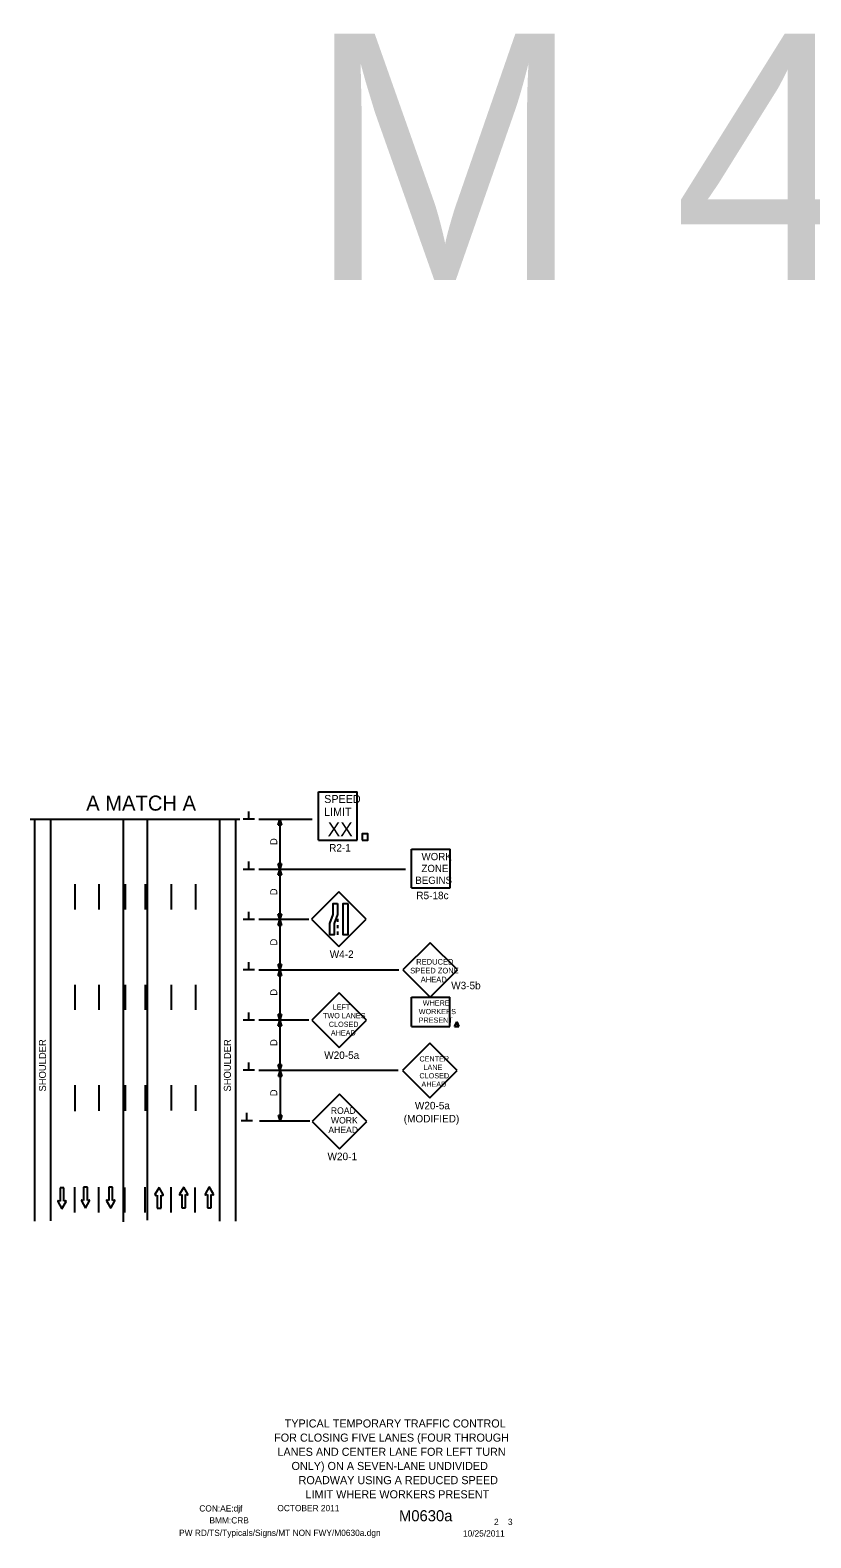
# Model space of a CAD drawing. Extents: x 20837 to 23689, y 414 to 2167.
# Drawn here: x 22136 to 22912, y 667 to 2167 of the extents above; entities that cross this region are included whole.
import ezdxf

# ---------------------------------------------------------------- set-up
doc = ezdxf.new("R2010")
doc.units = 0
for name, color, linetype in [('ALI_LEGAL_EX', 7, 'Continuous'), ('BORDER', 7, 'Continuous'), ('BORDER_SIGNAL_WO', 7, 'Continuous'), ('MT_SCRATCH_LEVEL_E', 7, 'Continuous'), ('PAVT_EDGE_EX', 7, 'Continuous'), ('TRAFFIC_SIGNS_PR', 7, 'Continuous'), ('TYPICAL_TEXT_DIMEN_PR', 7, 'Continuous')]:
    doc.layers.add(name, color=color, linetype=linetype)

msp = doc.modelspace()

# ---------------------------------------------------------------- linework, layer by layer
at = {"layer": 'ALI_LEGAL_EX'}
for points in [[(22180.1, 1317.4), (22180.1, 1292.4)], [(22204.1, 1317.4), (22204.1, 1292.4)], [(22230.1, 1317.4), (22230.1, 1292.4)], [(22250.1, 1317.4), (22250.1, 1292.4)], [(22276.1, 1317.4), (22276.1, 1292.4)], [(22300.1, 1317.4), (22300.1, 1292.4)], [(22180.1, 1217.4), (22180.1, 1192.4)], [(22204.1, 1217.4), (22204.1, 1192.4)], [(22230.1, 1217.4), (22230.1, 1192.4)], [(22250.1, 1217.4), (22250.1, 1192.4)], [(22276.1, 1217.4), (22276.1, 1192.4)], [(22300.1, 1217.4), (22300.1, 1192.4)], [(22180.1, 1117.4), (22180.1, 1091.6)], [(22204.1, 1117.4), (22204.1, 1091.9)], [(22230.1, 1117.4), (22230.1, 1091.9)], [(22250.1, 1117.4), (22250.1, 1091.9)], [(22276.1, 1117.4), (22276.1, 1092.2)], [(22300.1, 1117.4), (22300.1, 1091.9)], [(22180.1, 990.9), (22180.1, 1016)], [(22204, 990.9), (22204, 1016)], [(22229.9, 990.7), (22229.9, 1015.8)], [(22250.2, 990.9), (22250.2, 1016)], [(22276, 990.9), (22276, 1016)], [(22300, 990.7), (22300, 1015.8)]]:
    msp.add_lwpolyline(points, dxfattribs=at)
at = {"layer": 'BORDER'}
msp.add_line((22502.6, 746.5), (22502.6, 746.5), dxfattribs=at)
at = {"layer": 'BORDER_SIGNAL_WO'}
msp.add_line((22502.6, 740.2), (22502.6, 740.2), dxfattribs=at)
at = {"layer": 'MT_SCRATCH_LEVEL_E'}
for p, q in [((22169.2, 1015.4), (22165.5, 1015.4)), ((22165.5, 1015.4), (22165.5, 1002.2)), ((22169.2, 1015.4), (22165.5, 1015.4)), ((22165.5, 1015.4), (22165.5, 1002.2)), ((22169.2, 1002.2), (22169.2, 1015.4)), ((22169.2, 1002.2), (22169.2, 1015.4)), ((22192.7, 1016), (22188.9, 1016)), ((22188.9, 1016), (22188.9, 1002.7)), ((22192.7, 1016), (22188.9, 1016)), ((22188.9, 1016), (22188.9, 1002.7)), ((22192.7, 1002.7), (22192.7, 1016)), ((22192.7, 1002.7), (22192.7, 1016)), ((22217.8, 1016.1), (22214, 1016.1)), ((22214, 1016.1), (22214, 1002.8)), ((22217.8, 1016.1), (22214, 1016.1)), ((22214, 1016.1), (22214, 1002.8)), ((22217.8, 1002.8), (22217.8, 1016.1)), ((22217.8, 1002.8), (22217.8, 1016.1)), ((22264, 1015.8), (22259.9, 1008.6)), ((22264, 1015.8), (22259.9, 1008.6)), ((22260.4, 1007.9), (22262.1, 1008.2)), ((22260.4, 1007.9), (22262.1, 1008.2)), ((22262.1, 1008.2), (22262.1, 995)), ((22262.1, 1008.2), (22262.1, 995)), ((22268.1, 1008.6), (22264, 1015.8)), ((22268.1, 1008.6), (22264, 1015.8)), ((22265.9, 995), (22265.9, 1008.2)), ((22265.9, 1008.2), (22267.6, 1007.9)), ((22265.9, 995), (22265.9, 1008.2)), ((22265.9, 1008.2), (22267.6, 1007.9)), ((22288.5, 1016.2), (22284.4, 1009)), ((22288.5, 1016.2), (22284.4, 1009)), ((22284.9, 1008.3), (22286.7, 1008.6)), ((22284.9, 1008.3), (22286.7, 1008.6)), ((22286.7, 1008.6), (22286.7, 995.4)), ((22286.7, 1008.6), (22286.7, 995.4)), ((22292.7, 1009), (22288.5, 1016.2)), ((22292.7, 1009), (22288.5, 1016.2)), ((22290.4, 995.4), (22290.4, 1008.6)), ((22290.4, 1008.6), (22292.2, 1008.3)), ((22290.4, 995.4), (22290.4, 1008.6)), ((22290.4, 1008.6), (22292.2, 1008.3)), ((22313.8, 1016.3), (22309.7, 1009.1)), ((22313.8, 1016.3), (22309.7, 1009.1)), ((22310.2, 1008.4), (22312, 1008.7)), ((22310.2, 1008.4), (22312, 1008.7)), ((22312, 1008.7), (22312, 995.4)), ((22312, 1008.7), (22312, 995.4)), ((22318, 1009.1), (22313.8, 1016.3)), ((22318, 1009.1), (22313.8, 1016.3)), ((22315.7, 995.4), (22315.7, 1008.7)), ((22315.7, 1008.7), (22317.5, 1008.4)), ((22315.7, 995.4), (22315.7, 1008.7)), ((22315.7, 1008.7), (22317.5, 1008.4)), ((22163.2, 1001.8), (22167.4, 994.5)), ((22163.2, 1001.8), (22167.4, 994.5)), ((22165.5, 1002.2), (22163.7, 1002.5)), ((22165.5, 1002.2), (22163.7, 1002.5)), ((22167.4, 994.5), (22171.5, 1001.8)), ((22167.4, 994.5), (22171.5, 1001.8)), ((22171, 1002.5), (22169.2, 1002.2)), ((22171, 1002.5), (22169.2, 1002.2)), ((22186.7, 1002.3), (22190.8, 995.1)), ((22186.7, 1002.3), (22190.8, 995.1)), ((22188.9, 1002.7), (22187.1, 1003)), ((22188.9, 1002.7), (22187.1, 1003)), ((22190.8, 995.1), (22194.9, 1002.3)), ((22190.8, 995.1), (22194.9, 1002.3)), ((22194.4, 1003), (22192.7, 1002.7)), ((22194.4, 1003), (22192.7, 1002.7)), ((22211.8, 1002.4), (22215.9, 995.2)), ((22211.8, 1002.4), (22215.9, 995.2)), ((22214, 1002.8), (22212.2, 1003.1)), ((22214, 1002.8), (22212.2, 1003.1)), ((22215.9, 995.2), (22220, 1002.4)), ((22215.9, 995.2), (22220, 1002.4)), ((22219.5, 1003.1), (22217.8, 1002.8)), ((22219.5, 1003.1), (22217.8, 1002.8)), ((22262.1, 995), (22265.9, 995)), ((22262.1, 995), (22265.9, 995)), ((22286.7, 995.4), (22290.4, 995.4)), ((22286.7, 995.4), (22290.4, 995.4)), ((22312, 995.4), (22315.7, 995.4)), ((22312, 995.4), (22315.7, 995.4))]:
    msp.add_line(p, q, dxfattribs=at)
for centre, start, end in [((22260.3, 1008.4), 150.4248, 279.9638), ((22260.3, 1008.4), 150.4248, 279.9638), ((22267.7, 1008.4), 260.0362, 29.7731), ((22267.7, 1008.4), 260.0362, 29.7731), ((22284.8, 1008.8), 150.4248, 279.9638), ((22284.8, 1008.8), 150.4248, 279.9638), ((22292.3, 1008.8), 260.0362, 29.7731), ((22292.3, 1008.8), 260.0362, 29.7731), ((22310.1, 1008.8), 150.4248, 279.9638), ((22310.1, 1008.8), 150.4248, 279.9638), ((22317.6, 1008.8), 260.0362, 29.7731), ((22317.6, 1008.8), 260.0362, 29.7731), ((22163.6, 1002), 80.0362, 209.7731), ((22163.6, 1002), 80.0362, 209.7731), ((22171.1, 1002), 330.4248, 99.9638), ((22171.1, 1002), 330.4248, 99.9638), ((22187.1, 1002.6), 80.0362, 209.7731), ((22187.1, 1002.6), 80.0362, 209.7731), ((22194.5, 1002.6), 330.4248, 99.9638), ((22194.5, 1002.6), 330.4248, 99.9638), ((22212.2, 1002.7), 80.0362, 209.7731), ((22212.2, 1002.7), 80.0362, 209.7731), ((22219.6, 1002.7), 330.4248, 99.9638), ((22219.6, 1002.7), 330.4248, 99.9638)]:
    msp.add_arc(centre, 0.463, start, end, dxfattribs=at)
at = {"layer": 'PAVT_EDGE_EX'}
for p, q in [((22140.1, 1382.3), (22140.1, 982.1)), ((22156.1, 1382.3), (22156.1, 982.7)), ((22228.1, 1382.3), (22228.1, 981.5)), ((22252.1, 1382.3), (22252.1, 983.2)), ((22324.1, 1382.3), (22324.1, 982.1)), ((22340.1, 1382.3), (22340.1, 982.1))]:
    msp.add_line(p, q, dxfattribs=at)
at = {"layer": 'TRAFFIC_SIGNS_PR'}
for p, q in [((22422.5, 1409.4), (22460.9, 1409.4)), ((22422.5, 1361.4), (22422.5, 1409.4)), ((22460.9, 1361.4), (22460.9, 1409.4)), ((22422.5, 1361.4), (22460.9, 1361.4)), ((22515, 1314), (22515, 1352.4)), ((22515, 1352.4), (22553.4, 1352.4)), ((22553.4, 1314), (22553.4, 1352.4)), ((22442.8, 1309.8), (22415.6, 1282.7)), ((22469.9, 1282.7), (22442.8, 1309.8)), ((22515, 1314), (22553.4, 1314)), ((22415.6, 1282.7), (22442.8, 1255.5)), ((22441.5, 1283.2), (22441.5, 1280)), ((22441.5, 1276.8), (22441.5, 1273.6)), ((22442.8, 1255.5), (22469.9, 1282.7)), ((22441.5, 1270.4), (22441.5, 1267.2)), ((22533.6, 1259.3), (22506.5, 1232.2)), ((22560.8, 1232.2), (22533.6, 1259.3)), ((22506.5, 1232.2), (22533.6, 1205)), ((22533.6, 1205), (22560.8, 1232.2)), ((22443.1, 1209.3), (22415.9, 1182.2)), ((22470.3, 1182.2), (22443.1, 1209.3)), ((22514.9, 1205.1), (22553.3, 1205.1)), ((22514.9, 1175.8), (22514.9, 1205.1)), ((22553.3, 1175.8), (22553.3, 1205.1)), ((22415.9, 1182.2), (22443.1, 1155)), ((22443.1, 1155), (22470.3, 1182.2)), ((22514.9, 1175.8), (22553.3, 1175.8)), ((22533.3, 1159.3), (22506.1, 1132.1)), ((22560.4, 1132.1), (22533.3, 1159.3)), ((22506.1, 1132.1), (22533.3, 1105)), ((22533.3, 1105), (22560.4, 1132.1)), ((22443.3, 1108.7), (22416.1, 1081.5)), ((22470.5, 1081.5), (22443.3, 1108.7)), ((22416.1, 1081.5), (22443.3, 1054.3)), ((22443.3, 1054.3), (22470.5, 1081.5))]:
    msp.add_line(p, q, dxfattribs=at)
for points in [[(22465.9, 1361.4), (22471.5, 1361.4), (22471.5, 1367.6), (22465.9, 1367.6)], [(22441.5, 1298.4), (22441.5, 1287.2), (22438.2, 1278.3), (22438.2, 1267.2), (22433.7, 1267.2), (22433.7, 1278.3), (22437, 1287.2), (22437, 1298.4)], [(22451.7, 1298.4), (22451.7, 1267.2), (22447.2, 1267.2), (22447.2, 1298.4)]]:
    msp.add_lwpolyline(points, close=True, dxfattribs=at)
for points in [[(22560, 1180.7), (22557.8, 1175.8)], [(22557.8, 1175.8), (22560, 1180.7)], [(22557.8, 1175.8), (22562.2, 1175.8)], [(22562.2, 1175.8), (22557.8, 1175.8)], [(22562.2, 1175.8), (22560, 1180.7)], [(22560, 1180.7), (22562.2, 1175.8)]]:
    msp.add_lwpolyline(points, dxfattribs=at)
at = {"layer": 'TYPICAL_TEXT_DIMEN_PR'}
for p, q in [((22135.8, 1382.3), (22344.4, 1382.3)), ((22228.1, 1382.3), (22252.1, 1382.3)), ((22358.8, 1382.3), (22347.6, 1382.3)), ((22353.2, 1382.3), (22353.2, 1390)), ((22363.1, 1382.3), (22416.1, 1382.3)), ((22382.5, 1376.4), (22384.1, 1382.3)), ((22384.1, 1382.3), (22385.6, 1376.4)), ((22384.1, 1382.3), (22384.1, 1332.3)), ((22384.1, 1376.4), (22382.5, 1376.4)), ((22385.6, 1376.4), (22384.1, 1376.4)), ((22353.2, 1332.3), (22353.2, 1340)), ((22384.1, 1332.3), (22382.5, 1338.1)), ((22382.5, 1338.1), (22384.1, 1338.1)), ((22384.1, 1338.1), (22385.6, 1338.1)), ((22385.6, 1338.1), (22384.1, 1332.3)), ((22358.8, 1332.3), (22347.6, 1332.3)), ((22509.2, 1332.3), (22363.1, 1332.3)), ((22382.5, 1326.4), (22384.1, 1332.3)), ((22384.1, 1326.4), (22382.5, 1326.4)), ((22384.1, 1332.3), (22385.6, 1326.4)), ((22384.1, 1332.3), (22384.1, 1282.3)), ((22385.6, 1326.4), (22384.1, 1326.4)), ((22358.8, 1282.3), (22347.6, 1282.3)), ((22353.2, 1282.3), (22353.2, 1290)), ((22412.8, 1282.3), (22363.1, 1282.3)), ((22384.1, 1282.3), (22382.5, 1288.1)), ((22382.5, 1288.1), (22384.1, 1288.1)), ((22382.5, 1276.4), (22384.1, 1282.3)), ((22384.1, 1276.4), (22382.5, 1276.4)), ((22384.1, 1288.1), (22385.6, 1288.1)), ((22385.6, 1288.1), (22384.1, 1282.3)), ((22384.1, 1282.3), (22385.6, 1276.4)), ((22384.1, 1282.3), (22384.1, 1232.3)), ((22385.6, 1276.4), (22384.1, 1276.4)), ((22358.8, 1232.3), (22347.6, 1232.3)), ((22353.2, 1232.3), (22353.2, 1240)), ((22363.1, 1232.3), (22502.5, 1232.3)), ((22384.1, 1232.3), (22382.5, 1238.1)), ((22382.5, 1238.1), (22384.1, 1238.1)), ((22382.5, 1226.4), (22384.1, 1232.3)), ((22384.1, 1238.1), (22385.6, 1238.1)), ((22385.6, 1238.1), (22384.1, 1232.3)), ((22384.1, 1232.3), (22385.6, 1226.4)), ((22384.1, 1232.3), (22384.1, 1182.3)), ((22384.1, 1226.4), (22382.5, 1226.4)), ((22385.6, 1226.4), (22384.1, 1226.4)), ((22353.2, 1182.3), (22353.2, 1190)), ((22384.1, 1182.3), (22382.5, 1188.1)), ((22382.5, 1188.1), (22384.1, 1188.1)), ((22384.1, 1188.1), (22385.6, 1188.1)), ((22385.6, 1188.1), (22384.1, 1182.3)), ((22358.8, 1182.3), (22347.6, 1182.3)), ((22412.8, 1182.3), (22363.1, 1182.3)), ((22382.5, 1176.4), (22384.1, 1182.3)), ((22384.1, 1176.4), (22382.5, 1176.4)), ((22384.1, 1182.3), (22385.6, 1176.4)), ((22384.1, 1182.3), (22384.1, 1132.3)), ((22385.6, 1176.4), (22384.1, 1176.4)), ((22358.8, 1132.3), (22347.6, 1132.3)), ((22353.2, 1132.3), (22353.2, 1140)), ((22363.1, 1132.3), (22501.7, 1132.3)), ((22384.1, 1132.3), (22382.5, 1138.1)), ((22382.5, 1138.1), (22384.1, 1138.1)), ((22382.8, 1126), (22384.4, 1131.9)), ((22384.4, 1126), (22382.8, 1126)), ((22384.1, 1138.1), (22385.6, 1138.1)), ((22385.6, 1138.1), (22384.1, 1132.3)), ((22384.4, 1131.9), (22384.4, 1081.9)), ((22384.4, 1131.9), (22385.9, 1126)), ((22385.9, 1126), (22384.4, 1126)), ((22356.8, 1082.1), (22345.5, 1082.1)), ((22356.8, 1082.1), (22345.5, 1082.1)), ((22351.1, 1082.1), (22351.1, 1089.9)), ((22351.1, 1082.1), (22351.1, 1089.9)), ((22364, 1081.9), (22413.9, 1081.9)), ((22384.4, 1081.9), (22382.8, 1087.7)), ((22382.8, 1087.7), (22384.4, 1087.7)), ((22384.4, 1081.9), (22382.8, 1087.7)), ((22382.8, 1087.7), (22384.4, 1087.7)), ((22384.4, 1087.7), (22385.9, 1087.7)), ((22385.9, 1087.7), (22384.4, 1081.9)), ((22384.4, 1087.7), (22385.9, 1087.7)), ((22385.9, 1087.7), (22384.4, 1081.9))]:
    msp.add_line(p, q, dxfattribs=at)

# ---------------------------------------------------------------- texts
at = {"layer": 'BORDER_SIGNAL_WO'}
for s, height, p in [('TYPICAL TEMPORARY TRAFFIC CONTROL', 8.039, (22388.9, 776.9)), ('FOR CLOSING FIVE LANES (FOUR THROUGH', 8.039, (22378.4, 762.8)), ('LANES AND CENTER LANE FOR LEFT TURN', 8.039, (22381.7, 748.7)), ('ONLY) ON A SEVEN-LANE UNDIVIDED', 8.039, (22395.7, 734.6)), ('ROADWAY USING A REDUCED SPEED', 8.039, (22402.7, 720.5)), ('LIMIT WHERE WORKERS PRESENT', 8.039, (22409.6, 706.4)), ('CON:AE:djf', 6.2, (22304, 693.3)), ('    OCTOBER 2011    ', 6.2, (22372.4, 693.6)), ('    M0630a   ', 11, (22486.2, 683.6)), ('PW RD/TS/Typicals/Signs/MT NON FWY/M0630a.dgn    ', 6.2, (22283.9, 669)), ('BMM:CRB   ', 6.2, (22314.1, 681.4)), (' 2    3 ', 6.2, (22594.8, 679.9)), ('10/25/2011    ', 6.2, (22566.2, 668.4))]:
    msp.add_text(s, height=height, dxfattribs=at).set_placement(p)
at = {"layer": 'TRAFFIC_SIGNS_PR'}
for s, height, p in [('SPEED', 8, (22428.2, 1398.3)), ('LIMIT', 8, (22428.1, 1385.5)), ('XX', 14.03, (22431.6, 1365.2)), ('R2-1', 7.44, (22433.1, 1350)), ('WORK', 7.22, (22525, 1341.4)), ('ZONE', 7.22, (22524.9, 1329.6)), ('BEGINS', 7.22, (22518.8, 1317.8)), ('R5-18c', 7.44, (22519.8, 1302.6)), ('W4-2', 7.44, (22433.7, 1244.1)), ('SPEED ZONE', 5.6, (22513.7, 1228.7)), ('REDUCED', 5.6, (22519.7, 1237.5)), ('AHEAD', 5.6, (22524.2, 1219.9)), ('W3-5b', 7.44, (22554.5, 1213)), ('WHERE', 5.2, (22526.2, 1196.8)), ('TWO LANES', 5.2, (22427, 1184.1)), ('LEFT', 5.2, (22436.6, 1192.7)), ('WORKERS', 5.2, (22522.2, 1188.2)), ('CLOSED', 5.2, (22432.8, 1175.5)), ('AHEAD', 5.2, (22434.8, 1166.9)), ('PRESENT', 5.2, (22522.2, 1179.6)), ('W20-5a', 7.44, (22428.2, 1143.6)), ('CENTER', 5.2, (22522.9, 1141.1)), ('CLOSED', 5.2, (22522.9, 1124.3)), ('LANE', 5.2, (22526.9, 1132.7)), ('AHEAD', 5.2, (22524.9, 1115.9)), ('ROAD', 6.41, (22434.8, 1089)), ('W20-5a', 7.44, (22518.4, 1093.5)), ('WORK', 6.41, (22434.9, 1079.4)), ('(MODIFIED)', 7.44, (22507.3, 1080.5)), ('AHEAD', 6.41, (22432.3, 1069.8)), ('W20-1', 7.45, (22431.5, 1042.9))]:
    msp.add_text(s, height=height, dxfattribs=at).set_placement(p)
at = {"layer": 'TYPICAL_TEXT_DIMEN_PR'}
for s, height, p in [('M 48', 245.04, (22411.4, 1918.7)), ('A MATCH A', 15, (22191.5, 1390.7))]:
    msp.add_text(s, height=height, dxfattribs=at).set_placement(p)
for s, p in [('D', (22381.5, 1356.5)), ('D', (22381.5, 1306.5)), ('D', (22381.5, 1306.5)), ('D', (22381.5, 1256.5)), ('D', (22381.5, 1206.5)), ('SHOULDER', (22151.5, 1111.2)), ('SHOULDER', (22335.4, 1111.2)), ('D', (22381.5, 1156.5)), ('D', (22381.5, 1106.5))]:
    msp.add_text(s, height=7, rotation=90, dxfattribs=at).set_placement(p)

doc.saveas('drawing.dxf')
